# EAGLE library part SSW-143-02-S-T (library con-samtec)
THROUGH-HOLE .025" SQ POST SOCKET Source: Samtec SSW.pdf
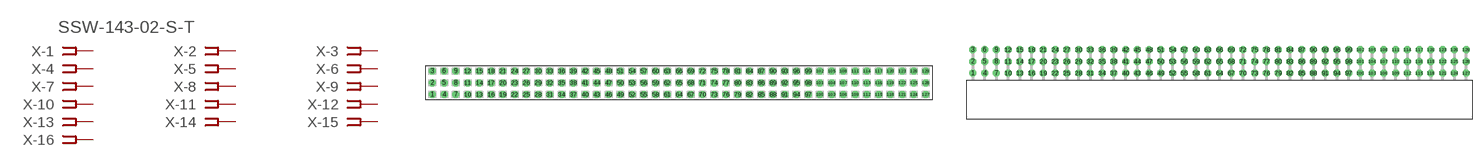
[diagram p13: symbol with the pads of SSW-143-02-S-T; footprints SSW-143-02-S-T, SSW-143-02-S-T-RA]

Designator prefix X; gates -1=FPINV -2=FPIN -3=FPIN -4=FPIN -5=FPIN -6=FPIN -7=FPIN -8=FPIN -9=FPIN -10=FPIN -11=FPIN -12=FPIN -13=FPIN -14=FPIN -15=FPIN -16=FPIN -17=FPIN -18=FPIN -19=FPIN -20=FPIN -21=FPIN -22=FPIN -23=FPIN -24=FPIN -25=FPIN -26=FPIN -27=FPIN -28=FPIN -29=FPIN -30=FPIN -31=FPIN -32=FPIN -33=FPIN -34=FPIN -35=FPIN -36=FPIN -37=FPIN -38=FPIN -39=FPIN -40=FPIN -41=FPIN -42=FPIN -43=FPIN -44=FPIN -45=FPIN -46=FPIN -47=FPIN -48=FPIN -49=FPIN -50=FPIN -51=FPIN -52=FPIN -53=FPIN -54=FPIN -55=FPIN -56=FPIN -57=FPIN -58=FPIN -59=FPIN -60=FPIN -61=FPIN -62=FPIN -63=FPIN -64=FPIN -65=FPIN -66=FPIN -67=FPIN -68=FPIN -69=FPIN -70=FPIN -71=FPIN -72=FPIN -73=FPIN -74=FPIN -75=FPIN -76=FPIN -77=FPIN -78=FPIN -79=FPIN -80=FPIN -81=FPIN -82=FPIN -83=FPIN -84=FPIN -85=FPIN -86=FPIN -87=FPIN -88=FPIN -89=FPIN -90=FPIN -91=FPIN -92=FPIN -93=FPIN -94=FPIN -95=FPIN -96=FPIN -97=FPIN -98=FPIN -99=FPIN -100=FPIN -101=FPIN -102=FPIN -103=FPIN -104=FPIN -105=FPIN -106=FPIN -107=FPIN -108=FPIN -109=FPIN -110=FPIN -111=FPIN -112=FPIN -113=FPIN -114=FPIN -115=FPIN -116=FPIN -117=FPIN -118=FPIN -119=FPIN -120=FPIN -121=FPIN -122=FPIN -123=FPIN -124=FPIN -125=FPIN -126=FPIN -127=FPIN -128=FPIN -129=FPIN

## SSW-143-02-S-T (OC_FARNELL: unknown; OC_NEWARK: unknown)  [SSW-143-02-S-T]
1  -1:1  pas
2  -2:1  pas
3  -3:1  pas
4  -4:1  pas
5  -5:1  pas
6  -6:1  pas
7  -7:1  pas
8  -8:1  pas
9  -9:1  pas
10  -10:1  pas
11  -11:1  pas
12  -12:1  pas
13  -13:1  pas
14  -14:1  pas
15  -15:1  pas
16  -16:1  pas
17  -17:1  pas
18  -18:1  pas
19  -19:1  pas
20  -20:1  pas
21  -21:1  pas
22  -22:1  pas
23  -23:1  pas
24  -24:1  pas
25  -25:1  pas
26  -26:1  pas
27  -27:1  pas
28  -28:1  pas
29  -29:1  pas
30  -30:1  pas
31  -31:1  pas
32  -32:1  pas
33  -33:1  pas
34  -34:1  pas
35  -35:1  pas
36  -36:1  pas
37  -37:1  pas
38  -38:1  pas
39  -39:1  pas
40  -40:1  pas
41  -41:1  pas
42  -42:1  pas
43  -43:1  pas
44  -44:1  pas
45  -45:1  pas
46  -46:1  pas
47  -47:1  pas
48  -48:1  pas
49  -49:1  pas
50  -50:1  pas
51  -51:1  pas
52  -52:1  pas
53  -53:1  pas
54  -54:1  pas
55  -55:1  pas
56  -56:1  pas
57  -57:1  pas
58  -58:1  pas
59  -59:1  pas
60  -60:1  pas
61  -61:1  pas
62  -62:1  pas
63  -63:1  pas
64  -64:1  pas
65  -65:1  pas
66  -66:1  pas
67  -67:1  pas
68  -68:1  pas
69  -69:1  pas
70  -70:1  pas
71  -71:1  pas
72  -72:1  pas
73  -73:1  pas
74  -74:1  pas
75  -75:1  pas
76  -76:1  pas
77  -77:1  pas
78  -78:1  pas
79  -79:1  pas
80  -80:1  pas
81  -81:1  pas
82  -82:1  pas
83  -83:1  pas
84  -84:1  pas
85  -85:1  pas
86  -86:1  pas
87  -87:1  pas
88  -88:1  pas
89  -89:1  pas
90  -90:1  pas
91  -91:1  pas
92  -92:1  pas
93  -93:1  pas
94  -94:1  pas
95  -95:1  pas
96  -96:1  pas
97  -97:1  pas
98  -98:1  pas
99  -99:1  pas
100  -100:1  pas
101  -101:1  pas
102  -102:1  pas
103  -103:1  pas
104  -104:1  pas
105  -105:1  pas
106  -106:1  pas
107  -107:1  pas
108  -108:1  pas
109  -109:1  pas
110  -110:1  pas
111  -111:1  pas
112  -112:1  pas
113  -113:1  pas
114  -114:1  pas
115  -115:1  pas
116  -116:1  pas
117  -117:1  pas
118  -118:1  pas
119  -119:1  pas
120  -120:1  pas
121  -121:1  pas
122  -122:1  pas
123  -123:1  pas
124  -124:1  pas
125  -125:1  pas
126  -126:1  pas
127  -127:1  pas
128  -128:1  pas
129  -129:1  pas

## SSW-143-02-S-TRA (OC_FARNELL: unknown; OC_NEWARK: unknown)  [SSW-143-02-S-T-RA]
Pads as for SSW-143-02-S-T

## Footprint SSW-143-02-S-T (pad centres in mm)
THROUGH-HOLE .025" SQ POST SOCKET Source: Samtec SSW.pdf
drill 1 pad 1.5 octagon: 1 -53.34,-2.54; 2 -53.34,0; 3 -53.34,2.54; 4 -50.8,-2.54; 5 -50.8,0; 6 -50.8,2.54; 7 -48.26,-2.54; 8 -48.26,0; 9 -48.26,2.54; 10 -45.72,-2.54; 11 -45.72,0; 12 -45.72,2.54; 13 -43.18,-2.54; 14 -43.18,0; 15 -43.18,2.54; 16 -40.64,-2.54; 17 -40.64,0; 18 -40.64,2.54; 19 -38.1,-2.54; 20 -38.1,0; 21 -38.1,2.54; 22 -35.56,-2.54; 23 -35.56,0; 24 -35.56,2.54; 25 -33.02,-2.54; 26 -33.02,0; 27 -33.02,2.54; 28 -30.48,-2.54; 29 -30.48,0; 30 -30.48,2.54; 31 -27.94,-2.54; 32 -27.94,0; 33 -27.94,2.54; 34 -25.4,-2.54; 35 -25.4,0; 36 -25.4,2.54; 37 -22.86,-2.54; 38 -22.86,0; 39 -22.86,2.54; 40 -20.32,-2.54; 41 -20.32,0; 42 -20.32,2.54; 43 -17.78,-2.54; 44 -17.78,0; 45 -17.78,2.54; 46 -15.24,-2.54; 47 -15.24,0; 48 -15.24,2.54; 49 -12.7,-2.54; 50 -12.7,0; 51 -12.7,2.54; 52 -10.16,-2.54; 53 -10.16,0; 54 -10.16,2.54; 55 -7.62,-2.54; 56 -7.62,0; 57 -7.62,2.54; 58 -5.08,-2.54; 59 -5.08,0; 60 -5.08,2.54; 61 -2.54,-2.54; 62 -2.54,0; 63 -2.54,2.54; 64 0,-2.54; 65 0,0; 66 0,2.54; 67 2.54,-2.54; 68 2.54,0; 69 2.54,2.54; 70 5.08,-2.54; 71 5.08,0; 72 5.08,2.54; 73 7.62,-2.54; 74 7.62,0; 75 7.62,2.54; 76 10.16,-2.54; 77 10.16,0; 78 10.16,2.54; 79 12.7,-2.54; 80 12.7,0; 81 12.7,2.54; 82 15.24,-2.54; 83 15.24,0; 84 15.24,2.54; 85 17.78,-2.54; 86 17.78,0; 87 17.78,2.54; 88 20.32,-2.54; 89 20.32,0; 90 20.32,2.54; 91 22.86,-2.54; 92 22.86,0; 93 22.86,2.54; 94 25.4,-2.54; 95 25.4,0; 96 25.4,2.54; 97 27.94,-2.54; 98 27.94,0; 99 27.94,2.54; 100 30.48,-2.54; 101 30.48,0; 102 30.48,2.54; 103 33.02,-2.54; 104 33.02,0; 105 33.02,2.54; 106 35.56,-2.54; 107 35.56,0; 108 35.56,2.54; 109 38.1,-2.54; 110 38.1,0; 111 38.1,2.54; 112 40.64,-2.54; 113 40.64,0; 114 40.64,2.54; 115 43.18,-2.54; 116 43.18,0; 117 43.18,2.54; 118 45.72,-2.54; 119 45.72,0; 120 45.72,2.54; 121 48.26,-2.54; 122 48.26,0; 123 48.26,2.54; 124 50.8,-2.54; 125 50.8,0; 126 50.8,2.54; 127 53.34,-2.54; 128 53.34,0; 129 53.34,2.54

## Footprint SSW-143-02-S-T-RA (pad centres in mm)
THROUGH-HOLE .025" SQ POST SOCKET Source: Samtec SSW.pdf
drill 1 pad 1.5 octagon: 1 -53.34,1.524; 2 -53.34,4.064; 3 -53.34,6.604; 4 -50.8,1.524; 5 -50.8,4.064; 6 -50.8,6.604; 7 -48.26,1.524; 8 -48.26,4.064; 9 -48.26,6.604; 10 -45.72,1.524; 11 -45.72,4.064; 12 -45.72,6.604; 13 -43.18,1.524; 14 -43.18,4.064; 15 -43.18,6.604; 16 -40.64,1.524; 17 -40.64,4.064; 18 -40.64,6.604; 19 -38.1,1.524; 20 -38.1,4.064; 21 -38.1,6.604; 22 -35.56,1.524; 23 -35.56,4.064; 24 -35.56,6.604; 25 -33.02,1.524; 26 -33.02,4.064; 27 -33.02,6.604; 28 -30.48,1.524; 29 -30.48,4.064; 30 -30.48,6.604; 31 -27.94,1.524; 32 -27.94,4.064; 33 -27.94,6.604; 34 -25.4,1.524; 35 -25.4,4.064; 36 -25.4,6.604; 37 -22.86,1.524; 38 -22.86,4.064; 39 -22.86,6.604; 40 -20.32,1.524; 41 -20.32,4.064; 42 -20.32,6.604; 43 -17.78,1.524; 44 -17.78,4.064; 45 -17.78,6.604; 46 -15.24,1.524; 47 -15.24,4.064; 48 -15.24,6.604; 49 -12.7,1.524; 50 -12.7,4.064; 51 -12.7,6.604; 52 -10.16,1.524; 53 -10.16,4.064; 54 -10.16,6.604; 55 -7.62,1.524; 56 -7.62,4.064; 57 -7.62,6.604; 58 -5.08,1.524; 59 -5.08,4.064; 60 -5.08,6.604; 61 -2.54,1.524; 62 -2.54,4.064; 63 -2.54,6.604; 64 0,1.524; 65 0,4.064; 66 0,6.604; 67 2.54,1.524; 68 2.54,4.064; 69 2.54,6.604; 70 5.08,1.524; 71 5.08,4.064; 72 5.08,6.604; 73 7.62,1.524; 74 7.62,4.064; 75 7.62,6.604; 76 10.16,1.524; 77 10.16,4.064; 78 10.16,6.604; 79 12.7,1.524; 80 12.7,4.064; 81 12.7,6.604; 82 15.24,1.524; 83 15.24,4.064; 84 15.24,6.604; 85 17.78,1.524; 86 17.78,4.064; 87 17.78,6.604; 88 20.32,1.524; 89 20.32,4.064; 90 20.32,6.604; 91 22.86,1.524; 92 22.86,4.064; 93 22.86,6.604; 94 25.4,1.524; 95 25.4,4.064; 96 25.4,6.604; 97 27.94,1.524; 98 27.94,4.064; 99 27.94,6.604; 100 30.48,1.524; 101 30.48,4.064; 102 30.48,6.604; 103 33.02,1.524; 104 33.02,4.064; 105 33.02,6.604; 106 35.56,1.524; 107 35.56,4.064; 108 35.56,6.604; 109 38.1,1.524; 110 38.1,4.064; 111 38.1,6.604; 112 40.64,1.524; 113 40.64,4.064; 114 40.64,6.604; 115 43.18,1.524; 116 43.18,4.064; 117 43.18,6.604; 118 45.72,1.524; 119 45.72,4.064; 120 45.72,6.604; 121 48.26,1.524; 122 48.26,4.064; 123 48.26,6.604; 124 50.8,1.524; 125 50.8,4.064; 126 50.8,6.604; 127 53.34,1.524; 128 53.34,4.064; 129 53.34,6.604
